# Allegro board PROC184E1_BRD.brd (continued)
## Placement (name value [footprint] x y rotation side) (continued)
C833  0.1uF  [CAP0201_0-5]  115.53 90.17 90 bottom
C834  0.1uF  [CAP0201_0-5]  128.68 90.2 45 bottom
C835  0.1uF  [CAP0201_0-5]  124.32 90.37 90 bottom
C836  0.1uF  [CAP0201_0-5]  119.92 89.43 135 bottom
C837  0.1uF  [CAP0201_0-5]  113.5 89.84 0 bottom
C838  0.01uF  [CAP0402_0-75]  158.68 89.78 270 bottom
C839  0.01uF  [CAP0402_0-75]  156.4 89.79 270 bottom
C840  0.1uF  [CAP0201_0-5]  135.59 102.29 90 bottom
C841  0.1uF  [CAP0201_0-5]  114.74 90.17 90 bottom
C844  0.1uF  [CAP0201_0-5]  125.13 90.17 90 bottom
C845  0.1uF  [CAP0201_0-5]  125.92 90.17 90 bottom
C846  0.01uF  [CAP0402_0-75]  145.09 88.01 270 bottom
C847  0.1uF  [CAP0201_0-5]  123.93 89.41 135 bottom
C848  0.1uF  [CAP0201_0-5]  128.76 88.16 0 bottom
C849  1uF  [CAP0402_0-75]  142.35 99.09 0 bottom
C850  0.1uF  [CAP0201_0-5]  117.12 90.17 90 bottom
C851  0.1uF  [CAP0201_0-5]  112.71 88.62 225 bottom
C853  0.1uF  [CAP0201_0-5]  121.55 89.08 180 bottom
C854  0.1uF  [CAP0201_0-5]  134.63 87.25 0 bottom
C855  0.1uF  [CAP0201_0-5]  128.15 90.6 45 bottom
C856  0.1uF  [CAP0201_0-5]  116.72 89.03 0 bottom
C857  0.1uF  [CAP0201_0-5]  115.45 88.77 270 bottom
C858  0.1uF  [CAP0402_0-75]  67.93 88.53 270 bottom
C859  0.1uF  [CAP0201_0-5]  114.28 89.03 0 bottom
C860  0.1uF  [CAP0201_0-5]  132.9 87.25 0 bottom
C862  0.1uF  [CAP0201_0-5]  127.08 89.41 45 bottom
C863  0.1uF  [CAP0201_0-5]  111.92 89.84 180 bottom
C864  0.1uF  [CAP0201_0-5]  129.5 89.41 45 bottom
C865  0.1uF  [CAP0201_0-5]  114.89 84.4 45 bottom
C866  0.1uF  [CAP0201_0-5]  114.08 83.27 315 bottom
C867  0.1uF  [CAP0201_0-5]  123.12 88.62 45 bottom
C870  0.1uF  [CAP0201_0-5]  119.16 87.55 0 bottom
C872  0.01uF  [CAP0402_0-75]  155.53 86.44 90 bottom
C873  0.1uF  [CAP0201_0-5]  113.6 84.25 180 bottom
C874  0.1uF  [CAP0201_0-5]  122.31 87.05 315 bottom
C875  0.1uF  [CAP0201_0-5]  113.17 87.81 270 bottom
C877  0.01uF  [CAP0402_0-75]  158.68 86.6 270 bottom
C878  0.1uF  [CAP0201_0-5]  125.51 80.65 45 bottom
C879  0.1uF  [CAP0402_0-75]  42.82 86.19 0 bottom
C880  0.1uF  [CAP0201_0-5]  129.45 87.43 0 bottom
C881  0.1uF  [CAP0201_0-5]  126.32 84.23 0 bottom
C882  0.1uF  [CAP0402_0-75]  67.93 85.54 270 bottom
C883  0.1uF  [CAP0402_0-75]  50.81 85.48 90 bottom
C884  0.01uF  [CAP0402_0-75]  145.22 85.2 270 bottom
C885  0.1uF  [CAP0201_0-5]  115.04 82.27 315 bottom
C886  0.1uF  [CAP0402_0-75]  42.83 84.97 0 bottom
C887  0.1uF  [CAP0201_0-5]  123.91 78.64 180 bottom
C888  0.1uF  [CAP0201_0-5]  119.13 79.43 180 bottom
C889  0.1uF  [CAP0201_0-5]  115.93 85.04 180 bottom
C890  0.01uF  [CAP0402_0-75]  155.74 84.02 270 bottom
C891  47uF  [CAP1210_2-75]  179 84.23 180 bottom
C892  47uF  [CAP1210_2-75]  173.16 84.23 0 bottom
C893  0.1uF  [CAP0201_0-5]  112.76 82.25 225 bottom
C894  0.1uF  [CAP0201_0-5]  124.32 87.81 90 bottom
C895  0.1uF  [CAP0201_0-5]  119.92 85.04 0 bottom
C896  0.1uF  [CAP0402_0-75]  67.93 83.48 270 bottom
C897  0.01uF  [CAP0402_0-75]  158.68 83.43 270 bottom
C898  0.1uF  [CAP0201_0-5]  117.1 81.56 90 bottom
C899  0.1uF  [CAP0201_0-5]  110.7 82.96 90 bottom
C900  0.1uF  [CAP0201_0-5]  111.97 76.2 180 bottom
C901  4.7uF  [CAP0402_0-75]  101.91 85.3 180 bottom
C902  0.1uF  [CAP0402_0-75]  25.92 82.84 0 bottom
C904  0.1uF  [CAP0201_0-5]  127.08 86.49 0 bottom
C905  10uF  [CAP0603_1-25]  109.94 63.88 180 bottom
C906  0.1uF  [CAP0402_0-75]  219.64 82.07 0 bottom
C907  0.1uF  [CAP0402_0-75]  241.41 81.98 270 bottom
C908  0.1uF  [CAP0201_0-5]  126.91 77.22 45 bottom
C909  0.1uF  [CAP0201_0-5]  116.72 83.03 225 bottom
C910  0.1uF  [CAP0201_0-5]  119.11 78.21 45 bottom
C911  0.1uF  [CAP0201_0-5]  110.32 70.23 45 bottom
C912  0.1uF  [CAP0402_0-75]  158.3 81.77 0 bottom
C913  0.01uF  [CAP0402_0-75]  144.33 89.66 90 bottom
C914  0.01uF  [CAP0402_0-75]  153.6 81.66 0 bottom
C915  0.01uF  [CAP0402_0-75]  148.4 81.66 180 bottom
C916  0.1uF  [CAP0201_0-5]  125.13 81.59 90 bottom
C917  9pF  [CAP0402_0-75]  186.62 81.69 90 bottom
C918  1uF  [CAP0402_0-75]  101.41 81.69 180 bottom
C919  0.1uF  [CAP0402_0-75]  229.93 81.29 90 bottom
C920  22uF  [CAP0805_1-25]  98.87 81.19 180 bottom
C921  0.1uF  [CAP0201_0-5]  114.13 82.35 315 bottom
C922  0.1uF  [CAP0201_0-5]  121.47 86.56 180 bottom
C923  10uF  [CAP0805_1-5]  15.5 81 270 bottom
C925  0.1uF  [CAP0201_0-5]  111.11 69.44 45 bottom
C926  0.1uF  [CAP0402_0-75]  17.27 80.88 270 bottom
C927  1uF  [CAP0402_0-75]  112.23 80.67 90 bottom
C928  10uF  [CAP0805_1-5]  177.86 80.68 180 bottom
C929  10uF  [CAP0805_1-5]  174.3 80.68 0 bottom
C930  1uF  [CAP0402_0-75]  101.41 80.68 180 bottom
C931  0.1uF  [CAP0402_0-75]  67.93 80.5 270 bottom
C932  0.1uF  [CAP0201_0-5]  121.57 85.83 180 bottom
C933  0.01uF  [CAP0402_0-75]  153.47 80.25 180 bottom
C934  0.01uF  [CAP0402_0-75]  151.06 80.25 180 bottom
C935  0.01uF  [CAP0402_0-75]  148.9 80.25 180 bottom
C936  0.01uF  [CAP0402_0-75]  146.61 80.25 180 bottom
C937  10uF  [CAP0603_1-25]  219.64 80.17 0 bottom
C938  0.1uF  [CAP0201_0-5]  111.16 80.21 180 bottom
C939  1uF  [CAP0402_0-75]  104.22 79.61 180 bottom
C940  0.1uF  [CAP0201_0-5]  111.9 68.61 45 bottom
C941  9pF  [CAP0402_0-75]  186.62 79.53 270 bottom
C942  10uF  [CAP0805_1-5#2]  156.27 79.53 0 bottom
C943  0.1uF  [CAP0201_0-5]  112.05 79.45 180 bottom
C944  0.1uF  [CAP0201_0-5]  128.71 81.03 0 bottom
C947  0.1uF  [CAP0201_0-5]  127.9 78.23 225 bottom
C948  1uF  [CAP0402_0-75]  153.48 79.28 0 bottom
C949  0.1uF  [CAP0402_0-75]  229.93 79.13 90 bottom
C950  0.1uF  [CAP0201_0-5]  113.52 70.23 225 bottom
C951  0.1uF  [CAP0402_0-75]  67.93 78.43 270 bottom
C952  0.01uF  [CAP0402_0-75]  153.48 78.34 0 bottom
C953  0.01uF  [CAP0402_0-75]  151.19 78.34 0 bottom
C954  0.01uF  [CAP0402_0-75]  149.03 78.34 0 bottom
C955  0.01uF  [CAP0402_0-75]  146.62 78.34 0 bottom
C957  0.1uF  [CAP0201_0-5]  111.16 78.99 135 bottom
C958  0.1uF  [CAP0201_0-5]  111.16 77.8 180 bottom
C959  0.1uF  [CAP0201_0-5]  127.97 82.63 0 bottom
C960  0.1uF  [CAP0201_0-5]  127.92 88.62 45 bottom
C962  0.1uF  [CAP0201_0-5]  133.54 68.22 0 bottom
C963  0.1uF  [CAP0402_0-75]  172.01 77.51 0 bottom
C965  0.1uF  [CAP0201_0-5]  110.37 77.04 180 bottom
C966  0.1uF  [CAP0201_0-5]  110.37 78.41 180 bottom
C967  0.1uF  [CAP0201_0-5]  125.74 86.82 135 bottom
C968  1uF  [CAP0402_0-75]  101.41 77.12 180 bottom
C969  0.1uF  [CAP0201_0-5]  127.14 75.03 315 bottom
C970  0.1uF  [CAP0201_0-5]  110.37 76.35 180 bottom
C971  0.1uF  [CAP0201_0-5]  115.76 75.54 0 bottom
C972  0.1uF  [CAP0201_0-5]  114.13 77.39 90 bottom
C973  2.2uF  [CAP0603_1]  176.21 76.74 270 bottom
C974  1uF  [CAP0402_0-75]  111.92 77.11 180 bottom
C976  10uF  [CAP0603_1-25]  112.68 63.88 180 bottom
C977  0.1uF  [CAP0402_0-75]  179.83 76.52 180 bottom
C978  0.01uF  [CAP0402_0-75]  157.75 76.43 0 bottom
C979  0.1uF  [CAP0402_0-75]  145.93 81.64 180 bottom
C980  0.1uF  [CAP0402_0-75]  21.83 76.41 270 bottom
C981  0.01uF  [CAP0402_0-75]  148.39 60.32 180 bottom
C982  0.01uF  [CAP0402_0-75]  153.6 60.32 0 bottom
C983  0.1uF  [CAP0201_0-5]  118.19 87.15 315 bottom
C984  0.1uF  [CAP0201_0-5]  115.93 76.15 180 bottom
C985  2.2uF  [CAP0603_1]  172.65 76.11 0 bottom
C986  0.1uF  [CAP0201_0-5]  113.44 65.53 270 bottom
C988  0.1uF  [CAP0402_0-75]  67.92 75.91 270 bottom
C989  0.1uF  [CAP0201_0-5]  111.11 74.68 180 bottom
C990  0.1uF  [CAP0201_0-5]  116.73 76.62 135 bottom
C992  0.1uF  [CAP0201_0-5]  113.76 76.4 135 bottom
C993  0.1uF  [CAP0201_0-5]  125.84 88.65 90 bottom
C994  47uF  [CAP1210_2-75]  185.61 75.6 90 bottom
C995  0.1uF  [CAP0201_0-5]  125.1 87.94 270 bottom
C996  0.1uF  [CAP0201_0-5]  120.33 86.21 90 bottom
C997  0.1uF  [CAP0201_0-5]  123.93 75.41 180 bottom
C999  0.1uF  [CAP0201_0-5]  117.18 77.45 90 bottom
C1000  0.01uF  [CAP0402_0-75]  160.97 75.22 270 bottom
C1001  10uF  [CAP0805_1-5]  182.79 75.09 90 bottom
C1002  0.1uF  [CAP0201_0-5]  111.11 75.44 180 bottom
C1003  0.1uF  [CAP0201_0-5]  118.32 75.41 180 bottom
C1004  0.1uF  [CAP0201_0-5]  114.28 65.53 270 bottom
C1005  0.1uF  [CAP0201_0-5]  113.75 75.59 135 bottom
C1006  0.1uF  [CAP0201_0-5]  112.3 75.03 90 bottom
C1007  0.1uF  [CAP0201_0-5]  125.54 75.01 135 bottom
C1008  0.1uF  [CAP0201_0-5]  111.08 81.05 180 bottom
C1009  0.1uF  [CAP0201_0-5]  113.44 67.08 270 bottom
C1010  0.01uF  [CAP0402_0-75]  158.41 74.63 90 bottom
C1011  0.1uF  [CAP0201_0-5]  134.17 90.35 315 bottom
C1012  0.1uF  [CAP0201_0-5]  110.47 73.91 180 bottom
C1014  0.1uF  [CAP0201_0-5]  112.76 72.24 180 bottom
C1015  2.2uF  [CAP0603_1]  173.36 74.07 0 bottom
C1016  0.1uF  [CAP0402_0-75]  67.92 73.85 270 bottom
C1017  0.1uF  [CAP0201_0-5]  114.28 67.08 270 bottom
C1018  4.7uF  [CAP0402_0-75]  101.41 73.82 180 bottom
C1019  0.1uF  [CAP0201_0-5]  112.71 73.08 180 bottom
C1020  0.1uF  [CAP0402_0-75]  21.07 73.62 0 bottom
C1021  0.1uF  [CAP0201_0-5]  115.48 73.43 270 bottom
C1022  0.1uF  [CAP0201_0-5]  114.71 72.62 270 bottom
C1023  0.1uF  [CAP0402_0-75]  25.56 73.01 180 bottom
C1024  0.01uF  [CAP0402_0-75]  145.22 63.88 270 bottom
C1025  2.2uF  [CAP0603_1]  173.36 72.8 0 bottom
C1026  1uF  [CAP0402_0-75]  101.41 72.68 180 bottom
C1027  0.1uF  [CAP0201_0-5]  109.58 75.44 180 bottom
C1028  0.1uF  [CAP0201_0-5]  113.95 73.33 270 bottom
C1029  0.1uF  [CAP0201_0-5]  124.65 74.5 180 bottom
C1031  22uF  [CAP0805_1-25]  96.07 72.04 180 bottom
C1032  0.1uF  [CAP0201_0-5]  116.72 73.03 0 bottom
C1033  0.01uF  [CAP0402_0-75]  155.53 65.1 90 bottom
C1034  0.1uF  [CAP0201_0-5]  111.92 73.74 180 bottom
C1035  2.2uF  [CAP0603_1]  173.36 71.53 0 bottom
C1036  1uF  [CAP0402_0-75]  101.41 71.53 180 bottom
C1037  0.01uF  [CAP0402_0-75]  158.41 71.45 90 bottom
C1038  10uF  [CAP1210_2-75]  215.45 71.28 0 bottom
C1039  2.2uF  [CAP0603_1]  171.48 71.08 270 bottom
C1040  0.1uF  [CAP0402_0-75]  67.93 70.4 270 bottom
C1041  1uF  [CAP0402_0-75]  101.41 76.05 180 bottom
C1042  4.7uF  [CAP0402_0-75]  98.99 70.39 180 bottom
C1043  0.1uF  [CAP0402_0-75]  43.47 70.24 0 bottom
C1044  0.01uF  [CAP0402_0-75]  145.09 66.67 270 bottom
C1045  0.1uF  [CAP0201_0-5]  98.99 69.5 180 bottom
C1046  1uF  [CAP0402_0-75]  115.53 71.91 270 bottom
C1047  1uF  [CAP0402_0-75]  114.71 74.22 270 bottom
C1048  1uF  [CAP0402_0-75]  113.9 71.86 270 bottom
C1049  10uF  [CAP0603_1-25]  43.7 68.84 0 bottom
C1050  0.1uF  [CAP0402_0-75]  200.55 68.74 90 bottom
C1051  0.01uF  [CAP0402_0-75]  144.31 68.29 90 bottom
C1052  0.1uF  [CAP0402_0-75]  67.93 68.34 270 bottom
C1053  0.01uF  [CAP0402_0-75]  158.41 68.28 90 bottom
C1054  0.01uF  [CAP0402_0-75]  156.37 68.5 270 bottom
C1055  10uF  [CAP1210_2-75]  215.45 67.72 0 bottom
C1056  0.1uF  [CAP0402_0-75]  56.96 67.62 270 bottom
C1057  0.1uF  [CAP0402_0-75]  239.55 67.47 0 bottom
C1058  0.1uF  [CAP0402_0-75]  237.49 67.47 0 bottom
C1059  10uF  [CAP0805_1-5]  177.86 67.47 180 bottom
C1060  10uF  [CAP0805_1-5]  174.3 67.47 0 bottom
C1062  0.1uF  [CAP0201_0-5]  126.6 74.22 270 bottom
C1063  0.1uF  [CAP0402_0-75]  42.5 66.13 0 bottom
C1064  0.1uF  [CAP0402_0-75]  56.96 65.64 90 bottom
C1065  0.1uF  [CAP0402_0-75]  67.93 65.58 270 bottom
C1066  0.01uF  [CAP0402_0-75]  156.39 71.24 270 bottom
C1067  1uF  [CAP0402_0-75]  96.93 65.18 180 bottom
C1068  0.01uF  [CAP0402_0-75]  145.22 71.62 270 bottom
C1069  10uF  [CAP0603_1]  158.41 64.47 90 bottom
C1070  1uF  [CAP0402_0-75]  116.38 63.5 270 bottom
C1071  47uF  [CAP1210_2-75]  179 63.99 180 bottom
C1072  47uF  [CAP1210_2-75]  173.16 63.91 0 bottom
C1073  0.1uF  [CAP0402_0-75]  67.93 63.52 270 bottom
C1074  0.01uF  [CAP0402_0-75]  145.83 73.61 90 bottom
C1075  0.1uF  [CAP0402_0-75]  194.24 61.83 270 bottom
C1077  1uF  [CAP0402_0-75]  139.45 57.33 270 bottom
C1078  1uF  [CAP0402_0-75]  110.63 59.26 270 bottom
C1079  0.1uF  [CAP0402_0-75]  130.39 49 180 top
C1080  1uF  [CAP0402_0-75]  119.54 48.89 180 top
C1081  0.1uF  [CAP0402_0-75]  144.97 75.61 270 bottom
C1082  0.1uF  [CAP0402_0-75]  43.37 61.12 0 bottom
C1083  0.01uF  [CAP0402_0-75]  149.53 76.45 0 bottom
C1084  0.01uF  [CAP0402_0-75]  152.33 76.45 180 bottom
C1085  0.01uF  [CAP0402_0-75]  154.87 76.45 180 bottom
C1086  0.1uF  [CAP0402_0-75]  130.39 47.81 180 top
C1089  10uF  [CAP0603_1-25]  43.49 59.72 0 bottom
C1090  0.01uF  [CAP0402_0-75]  148.24 59.34 180 bottom
C1091  0.01uF  [CAP0402_0-75]  155.61 58.75 0 bottom
C1092  0.01uF  [CAP0402_0-75]  153.45 58.75 0 bottom
C1093  10uF  [CAP0805_1-5#2]  137.98 56.93 270 bottom
C1095  0.1uF  [CAP0402_0-75]  137.6 45.23 0 bottom
C1096  0.1uF  [CAP0402_0-75]  135.54 45.23 180 bottom
C1097  0.1uF  [CAP0402_0-75]  56.98 56.2 0 bottom
C1098  4.7uF  [CAP0402_0-75]  135.54 44.09 180 bottom
C1105  0.1uF  [CAP0402_0-75]  193.41 54.01 90 bottom
C1117  0.1uF  [CAP0402_0-75]  54.34 50.12 180 bottom
C1118  0.1uF  [CAP0402_0-75]  64.19 49.61 0 bottom
C1120  0.1uF  [CAP0201_0-5]  71.94 49.44 90 bottom
C1122  0.01uF  [CAP0402_0-75]  194.09 49.19 0 bottom
C1123  0.1uF  [CAP0402_0-75]  13.35 48.72 90 bottom
C1124  0.1uF  [CAP0402_0-75]  26.06 47.64 90 bottom
C1131  0.1uF  [CAP0402_0-75]  54.2 45.37 0 bottom
C1134  0.1uF  [CAP0402_0-75]  63.86 44.76 270 bottom
C1135  0.1uF  [CAP0201_0-5]  72.07 44.56 90 bottom
C1137  0.1uF  [CAP0402_0-75]  19.4 44.25 90 bottom
C1138  0.1uF  [CAP0402_0-75]  17.98 44.25 270 bottom
C1161  0.01uF  [CAP0402_0-75]  45.99 41.75 180 bottom
C1162  10uF  [CAP0603_1-25]  204.83 41.47 0 bottom
C1163  10uF  [CAP0603_1-25]  199.37 40.43 180 bottom
C1164  0.1uF  [CAP0402_0-75]  204.71 39.93 0 bottom
C1165  0.1uF  [CAP0402_0-75]  199.37 38.89 180 bottom
C1166  10uF  [CAP1210_2-75]  11.43 38.77 90 bottom
C1167  0.1uF  [CAP0603_1]  14.35 38.64 90 bottom
C1168  10uF  [CAP0603_1-25]  43.67 37.59 90 bottom
C1169  0.01uF  [CAP0402_0-75]  81.55 35.34 0 bottom
C1170  0.1uF  [CAP0402_0-75]  43.87 35.34 270 bottom
C1171  0.1uF  [CAP0402_0-75]  42.6 35.34 270 bottom
C1172  18pF  [CAP0402_0-75]  139 34.58 0 bottom
C1173  18pF  [CAP0402_0-75]  137.06 34.58 180 bottom
C1174  0.1uF  [CAP0402_0-75]  183.24 32.42 180 bottom
C1175  0.1uF  [CAP0402_0-75]  166.94 31.45 0 bottom
C1176  1uF  [CAP0402_0-75]  83.65 31.4 180 bottom
C1177  0.1uF  [CAP0402_0-75]  57.94 30.46 270 bottom
C1178  1uF  [CAP0402_0-75]  95.33 30.34 90 bottom
C1179  10uF  [CAP0805_1-5]  93.56 30.34 90 bottom
C1180  1uF  [CAP0402_0-75]  69.68 30.34 90 bottom
C1181  10uF  [CAP0805_1-5]  67.9 30.34 90 bottom
C1182  0.1uF  [CAP0402_0-75]  83.65 30.13 0 bottom
C1183  1uF  [CAP0402_0-75]  167.7 29.63 90 bottom
C1184  0.1uF  [CAP0402_0-75]  166.43 29.63 90 bottom
C1185  0.1uF  [CAP0402_0-75]  160.72 29.03 90 bottom
C1186  10uF  [CAP0805_1-5]  90.08 28.76 90 bottom
C1187  10uF  [CAP0805_1-5]  64.42 28.76 90 bottom
C1188  1uF  [CAP0402_0-75]  91.78 28.71 90 bottom
C1189  1uF  [CAP0402_0-75]  66.12 28.71 90 bottom
C1190  0.1uF  [CAP0402_0-75]  93.91 27.77 180 bottom
C1191  0.1uF  [CAP0402_0-75]  68.26 27.77 180 bottom
C1192  2.2uF  [CAP0402_0-75]  180.63 27.34 90 bottom
C1193  3300pF  [CAP0402_0-75]  26.65 27.33 0 bottom
C1194  10uF  [CAP0805_1-5]  35.91 26.61 270 bottom
C1195  10uF  [CAP0805_1-5]  33.73 26.61 270 bottom
C1196  0.01uF  [CAP0402_0-75]  87.92 25.73 90 bottom
C1197  0.1uF  [CAP0402_0-75]  93.91 25.71 180 bottom
C1198  0.1uF  [CAP0402_0-75]  68.26 25.71 180 bottom
C1199  0.1uF  [CAP0402_0-75]  136.56 25.53 180 bottom
C1200  1uF  [CAP0402_0-75]  58.35 25.48 180 bottom
C1201  680pF  [CAP0402_0-75]  29.07 25.23 0 bottom
C1202  680pF  [CAP0402_0-75]  24.55 25.16 0 bottom
C1203  4.7uF  [CAP0603_1]  60.5 25.1 270 bottom
C1204  0.1uF  [CAP0402_0-75]  83.65 24.92 0 bottom
C1205  0.1uF  [CAP0402_0-75]  230.38 24.72 90 bottom
C1206  0.1uF  [CAP0402_0-75]  58.35 24.21 0 bottom
C1207  27pF  [CAP0402_0-75]  93.32 24.04 270 bottom
C1208  27pF  [CAP0402_0-75]  67.66 24.04 270 bottom
C1209  1uF  [CAP0402_0-75]  117.96 23.57 180 bottom
C1210  10uF  [CAP0805_1-5]  83.65 23.27 180 bottom
C1211  10uF  [CAP0805_1-5]  31.1 23.1 90 bottom
C1212  10uF  [CAP0603_1-25]  176.11 22.99 90 bottom
C1213  1uF  [CAP0402_0-75]  177.69 22.99 90 bottom
C1214  0.1uF  [CAP0402_0-75]  224.18 22.63 90 bottom
C1215  220uF_10V  [CAPT3528T_1-25]  19.48 22.56 180 bottom
C1216  0.1uF  [CAP0402_0-75]  214.62 22.25 270 bottom
C1217  0.1uF  [CAP0402_0-75]  182.67 22.18 270 bottom
C1218  27pF  [CAP0402_0-75]  93.32 22 90 bottom
C1219  27pF  [CAP0402_0-75]  67.66 22 90 bottom
C1220  0.01uF  [CAP0402_0-75]  62.62 19.81 90 bottom
C1221  0.1uF  [CAP0402_0-75]  101.11 19.57 270 bottom
C1222  0.1uF  [CAP0402_0-75]  99.61 19.57 270 bottom
C1223  0.1uF  [CAP0402_0-75]  98.11 19.57 270 bottom
C1224  0.1uF  [CAP0402_0-75]  75.46 19.57 270 bottom
C1225  0.1uF  [CAP0402_0-75]  73.96 19.57 270 bottom
C1226  0.1uF  [CAP0402_0-75]  72.46 19.57 270 bottom
C1227  10uF  [CAP0805_1-5]  44.11 19.31 180 bottom
C1228  0.1uF  [CAP0402_0-75]  58.35 19.01 0 bottom
C1229  220uF_10V  [CAPT3528T_1-25]  19.48 18.88 180 bottom
C1230  0.1uF  [CAP0402_0-75]  32.12 17.39 0 bottom
C1231  10uF  [CAP0805_1-5]  58.35 17.36 180 bottom
C1232  0.1uF  [CAP0402_0-75]  188.42 17.14 270 bottom
C1233  680pF  [CAP0402_0-75]  30.07 16.26 0 bottom
C1234  680pF  [CAP0402_0-75]  25.62 16.26 0 bottom
C1235  0.1uF  [CAP0402_0-75]  197.71 16.21 270 bottom
C1236  0.1uF  [CAP0402_0-75]  214.55 16.17 270 bottom
C1237  0.1uF  [CAP0402_0-75]  23.44 16.02 180 bottom
C1238  10uF  [CAP0805_1-5]  42.1 15.45 0 bottom
C1239  0.1uF  [CAP0402_0-75]  223.8 15.4 270 bottom
C1240  10uF  [CAP0805_1-5]  56.57 15.1 0 bottom
C1241  0.1uF  [CAP0402_0-75]  231.84 14.72 180 bottom
C1242  3300pF  [CAP0402_0-75]  27.84 14.17 0 bottom
C1243  4.7uF  [CAP0603_1]  187.9 13.27 270 bottom
C1244  4.7uF  [CAP0603_1]  214 13.27 270 bottom
C1245  4.7uF  [CAP0603_1]  190.54 13.23 90 bottom
C1246  4.7uF  [CAP0603_1]  216.64 13.23 90 bottom
C1247  1000pF  [CAP1206_1-75]  88.97 12.27 270 bottom
C1248  1000pF  [CAP1206_1-75]  63.9 12.24 270 bottom
C1249  10uF  [CAP0603_1-25]  21.27 12.1 180 bottom
C1250  0.1uF  [CAP0402_0-75]  21.27 10.57 180 bottom
C1251  0.01uF  [CAP0402_0-75]  197.29 10.45 0 bottom
C1252  0.1uF  [CAP0402_0-75]  199.96 10.25 0 bottom
C1253  0.01uF  [CAP0402_0-75]  219.9 9.96 0 bottom
C1254  0.1uF  [CAP0402_0-75]  222.56 9.76 0 bottom
C1255  2.2uF  [CAP0402_0-75]  199.96 9.1 0 bottom
C1256  2.2uF  [CAP0402_0-75]  222.56 8.62 0 bottom
C1257  10uF  [CAP0805_1-5]  192.08 7.65 90 bottom
C1258  0.1uF  [CAP0402_0-75]  193.79 7.65 90 bottom
C1259  0.1uF  [CAP0402_0-75]  21.27 7.27 180 bottom
C1260  10uF  [CAP0805_1-5]  214.69 7.17 90 bottom
C1261  0.1uF  [CAP0402_0-75]  216.39 7.17 90 bottom
C1262  10uF  [CAP0805_1-5]  28.94 7.14 270 bottom
C1263  10uF  [CAP0805_1-5]  26.75 7.14 270 bottom
C1264  0.1uF  [CAP0402_0-75]  202.84 6.35 180 bottom
C1265  10uF  [CAP0603_1-25]  21.27 5.75 180 bottom
C1266  0.1uF  [CAP0402_0-75]  121.53 173.82 270 bottom
C1267  0.1uF  [CAP0402_0-75]  96.01 172.83 180 bottom
C1268  0.1uF  [CAP0402_0-75]  130.71 26.54 90 bottom
C1269  0.1uF  [CAP0402_0-75]  73.47 66.67 180 top
C1271  0.1uF  [CAP0402_0-75]  67.88 92.2 270 top
C1290  100uF  [CAP1210_3]  96.86 91.59 270 top
C1291  100uF  [CAP1210_3]  90.36 92.53 270 top
C1292  100uF  [CAP1210_3]  112.45 106.96 270 top
C1293  100uF  [CAP1210_3]  113.67 115.77 180 top
C2582  100uF  [CAP1210_3]  137.88 106.97 270 bottom
C2583  100uF  [CAP1210_3]  148.27 106.97 270 bottom
C2584  100uF  [CAP1210_3]  144.71 106.97 270 bottom
C2585  100uF  [CAP1210_3]  141.16 106.97 270 bottom
C2586  100uF  [CAP1210_3]  95.56 108.49 0 bottom
C2587  100uF  [CAP1210_3]  95.56 101.89 0 bottom
C2588  100uF  [CAP1210_3]  96.86 90.74 270 bottom
C2589  100uF  [CAP1210_3]  95.56 105.19 0 bottom
C2590  100uF  [CAP1210_3]  90.23 92.53 270 bottom
C2591  100uF  [CAP1210_3]  93.5 92.53 270 bottom
C2592  100uF  [CAP1210_3]  95.56 98.58 0 bottom
D1  TPD1E05U06DPY  [DIO_DFN0402_0-5]  142.82 186.11 90 top
D2  TPD1E05U06DPY  [DIO_DFN0402_0-5]  155.82 186.11 90 top
D3  TPD1E05U06DPY  [DIO_DFN0402_0-5]  142.82 184.65 270 top
D4  TPD1E05U06DPY  [DIO_DFN0402_0-5]  155.82 184.65 270 top
D5  TPD1E05U06DPY  [DIO_DFN0402_0-5]  146.34 180.52 180 top
D6  TPD1E05U06DPY  [DIO_DFN0402_0-5]  147.8 180.52 0 top
D7  TPD1E05U06DPY  [DIO_DFN0402_0-5]  150.84 180.52 180 top
D8  TPD1E05U06DPY  [DIO_DFN0402_0-5]  152.3 180.52 0 top
D9  TPD1E05U06DPY  [DIO_DFN0402_0-5]  89.31 173.71 180 top
D10  TPD1E05U06DPY  [DIO_DFN0402_0-5]  90.98 173.71 0 top
D11  TPD1E05U06DPY  [DIO_DFN0402_0-5]  95.25 173.71 180 top
D12  TPD1E05U06DPY  [DIO_DFN0402_0-5]  96.93 173.71 0 top
D13  TPD1E05U06DPY  [DIO_DFN0402_0-5]  115.18 173.71 180 top
D14  TPD1E05U06DPY  [DIO_DFN0402_0-5]  116.85 173.71 0 top
D15  TPD1E05U06DPY  [DIO_DFN0402_0-5]  121.13 173.71 180 top
D16  TPD1E05U06DPY  [DIO_DFN0402_0-5]  122.8 173.71 0 top
D17  TPD1E05U06DPY  [DIO_DFN0402_0-5]  86.38 172.31 180 top
D18  TPD1E05U06DPY  [DIO_DFN0402_0-5]  88.06 172.31 0 top
D19  TPD1E05U06DPY  [DIO_DFN0402_0-5]  112.26 172.31 180 top
D20  TPD1E05U06DPY  [DIO_DFN0402_0-5]  113.93 172.31 0 top
D21  TPD1E05U06DPY  [DIO_DFN0402_0-5]  92.25 172.06 180 top
D22  TPD1E05U06DPY  [DIO_DFN0402_0-5]  93.93 172.06 0 top
D23  TPD1E05U06DPY  [DIO_DFN0402_0-5]  98.3 172.06 180 top
D24  TPD1E05U06DPY  [DIO_DFN0402_0-5]  99.98 172.06 0 top
D25  TPD1E05U06DPY  [DIO_DFN0402_0-5]  118.12 172.06 180 top
D26  TPD1E05U06DPY  [DIO_DFN0402_0-5]  119.8 172.06 0 top
D27  TPD1E05U06DPY  [DIO_DFN0402_0-5]  124.17 172.06 180 top
D28  TPD1E05U06DPY  [DIO_DFN0402_0-5]  125.85 172.06 0 top
D29  SMCJ58CA  [DIO_SMC_2-7]  227.52 171.97 0 top
D30  SZMM3Z10VST1G  [DIO_SOD323_1-1]  164.01 162.7 0 top
D31  RBR1MM60A  [DIO_SOD123F_0-9]  196.36 152.76 270 top
D32  RBR1MM60A  [DIO_SOD123F_0-9]  196.36 147.94 90 top
D33  TPD1E10B06DPYR  [DIO_DFN0402_0-5]  16.57 123.18 90 top
D34  RBR1MM60A  [DIO_SOD123F_0-9]  223.55 107.2 270 top
D35  RBR1MM60A  [DIO_SOD123F_0-9]  223.55 102.37 90 top
D36  SZMM3Z10VST1G  [DIO_SOD323_1-1]  89.73 64.28 180 top
D37  TPD1E10B06DPYR  [DIO_DFN0402_0-5]  19.71 59.21 90 top
D38  RBR1MM60A  [DIO_SOD123F_0-9]  212.5 58.15 270 top
D39  DDZ9678-7  [DIO_SOD123_1-5]  113.09 13.21 270 top
D40  MBRS410LT3G  [DIO_SMC]  170.29 183.8 270 bottom
D41  BZT52C13S  [DIO_SOD323]  206.82 147.53 180 bottom
D42  1N4148W-7-F  [DIO_SOD123_1-4]  18.04 37.62 180 bottom
D43  1N4148W-7-F  [DIO_SOD123_1-4]  18.04 35.08 180 bottom
D44  1N4148W-7-F  [DIO_SOD123_1-4]  14.1 33.56 270 bottom
D45  1N4148W-7-F  [DIO_SOD123_1-4]  11.31 33.56 270 bottom
F1  6.3A  [FUSEH_154004_380X200_SMD_3-9]  219.26 169.3 270 top
F2  6.3A  [FUSEH_154004_380X200_SMD_3-9]  203.01 165.89 90 top
FL1  0.47uF  [EMIFIL_NFM21P_0805]  114.52 162.82 180 top
FL2  0.47uF  [EMIFIL_NFM21P_0805]  88.07 161.7 270 top
FL3  0.47uF  [EMIFIL_NFM21P_0805]  101.79 160.14 270 top
FL4  0.47uF  [EMIFIL_NFM21P_0805]  101.79 156.71 90 top
FL5  0.47uF  [EMIFIL_NFM21P_0805]  84.51 151.71 0 top
FL6  0.47uF  [EMIFIL_NFM21P_0805]  113.25 150.63 180 top
FL7  120E  [EMIFIL_BLM18P_0603_0-8]  107.15 136.66 270 top
FL8  0.47uF  [EMIFIL_NFM21P_0805]  53.91 121.98 270 top
FL9  0.47uF  [EMIFIL_NFM21P_0805]  66.1 120.71 270 top
FL10  10uF  [EMIFIL_NFM18C_0603_0-7_TI]  165.46 119.22 270 top
FL11  10uF  [EMIFIL_NFM18C_0603_0-7_TI]  166.86 119.22 270 top
FL12  10uF  [EMIFIL_NFM18C_0603_0-7_TI]  172.45 119.22 270 top
FL13  10uF  [EMIFIL_NFM18C_0603_0-7_TI]  173.85 119.22 270 top
FL14  10uF  [EMIFIL_NFM18C_0603_0-7_TI]  176.89 119.22 270 top
FL15  10uF  [EMIFIL_NFM18C_0603_0-7_TI]  178.29 119.22 270 top
FL16  10uF  [EMIFIL_NFM18C_0603_0-7_TI]  183.88 119.22 270 top
FL17  10uF  [EMIFIL_NFM18C_0603_0-7_TI]  185.28 119.22 270 top
FL18  10uF  [EMIFIL_NFM18C_0603_0-7_TI]  188.07 119.22 270 top
FL19  10uF  [EMIFIL_NFM18C_0603_0-7_TI]  189.47 119.22 270 top
FL20  10uF  [EMIFIL_NFM18C_0603_0-7_TI]  195.06 119.22 270 top
FL21  10uF  [EMIFIL_NFM18C_0603_0-7_TI]  196.45 119.22 270 top
FL22  10uF  [EMIFIL_NFM18C_0603_0-7_TI]  75.88 117.89 0 top
FL23  10uF  [EMIFIL_NFM18C_0603_0-7_TI]  75.88 116.49 0 top
FL24  10uF  [EMIFIL_NFM18C_0603_0-7_TI]  75.88 110.9 0 top
FL25  10uF  [EMIFIL_NFM18C_0603_0-7_TI]  75.88 109.51 0 top
FL26  0.47uF  [EMIFIL_NFM21P_0805]  56.38 109.13 0 top
FL27  0.47uF  [EMIFIL_NFM21P_0805]  59.91 109.13 180 top
FL32  10uF  [EMIFIL_NFM18C_0603_0-7_TI]  75.88 106.71 0 top
FL33  10uF  [EMIFIL_NFM18C_0603_0-7_TI]  75.88 105.32 0 top
FL34  10uF  [EMIFIL_NFM18C_0603_0-7_TI]  75.88 99.73 0 top
FL35  10uF  [EMIFIL_NFM18C_0603_0-7_TI]  75.88 98.33 0 top
FL40  1uF  [EMIFIL_NFM15CC_0402_0-5_TI]  173.4 87.41 180 top
FL41  1uF  [EMIFIL_NFM15CC_0402_0-5_TI]  178.76 87.41 180 top
FL42  120E  [EMIFIL_BLM15A_0402_0-6]  96.45 70.9 0 top
FL43  10uF  [EMIFIL_NFM18C_0603_0-7_TI]  88.83 68.23 0 top
FL44  10uF  [EMIFIL_NFM18C_0603_0-7_TI]  91.75 68.23 0 top
FL45  1uF  [EMIFIL_NFM15CC_0402_0-5_TI]  94.17 68.23 0 top
FL46  1uF  [EMIFIL_NFM15CC_0402_0-5_TI]  96.33 68.23 0 top
FL47  1uF  [EMIFIL_NFM15CC_0402_0-5_TI]  173.4 65.9 0 top
FL48  1uF  [EMIFIL_NFM15CC_0402_0-5_TI]  178.76 65.9 0 top
FL56  120E  [EMIFIL_BLM15A_0402_0-6]  40.83 29.83 180 top
FL57  120E  [EMIFIL_BLM15A_0402_0-6]  56.37 19.41 270 top
FL58  120E  [EMIFIL_BLM15A_0402_0-6]  59.11 9.18 270 top
FL59  120E  [EMIFIL_BLM15A_0402_0-6]  24.57 7.75 90 top
FL60  120E  [EMIFIL_BLM18A_0603]  142.02 155.35 90 bottom
FL61  120E  [EMIFIL_BLM18A_0603]  153.09 151.54 90 bottom
FL62  120E  [EMIFIL_BLM18A_0603]  137.68 150.43 90 bottom
FL63  120E  [EMIFIL_BLM18P_0603_0-8]  99.24 134.92 180 bottom
FL65  120E  [EMIFIL_BLM15A_0402_0-6]  129.6 113.29 270 bottom
FL66  120E  [EMIFIL_BLM15A_0402_0-6]  126.04 113.29 270 bottom
FL67  120E  [EMIFIL_BLM15A_0402_0-6]  122.49 113.29 90 bottom
FL70  120E  [EMIFIL_BLM15A_0402_0-6]  114.13 113.29 270 bottom
FL71  120E  [EMIFIL_BLM15A_0402_0-6]  111.72 113.29 270 bottom
FL76  120E  [EMIFIL_BLM15A_0402_0-6]  106.76 111.29 90 bottom
FL81  120E  [EMIFIL_BLM15A_0402_0-6]  106.51 108.85 270 bottom
FL82  120E  [EMIFIL_BLM15A_0402_0-6]  132.01 107.97 270 bottom
FL83  120E  [EMIFIL_BLM15A_0402_0-6]  135.57 107.97 270 bottom
FL84  120E  [EMIFIL_BLM15A_0402_0-6]  128.46 107.97 270 bottom
FL86  120E  [EMIFIL_BLM15A_0402_0-6]  121.34 107.97 90 bottom
FL87  120E  [EMIFIL_BLM15A_0402_0-6]  117.79 107.97 270 bottom
FL89  120E  [EMIFIL_BLM15A_0402_0-6]  110.57 107.97 270 bottom
FL94  120E  [EMIFIL_BLM15A_0402_0-6]  149.04 103.43 270 bottom
FL95  0E  [RES0402_0-5#2]  159.41 103.45 90 bottom
FL96  120E  [EMIFIL_BLM15A_0402_0-6]  155.95 103.45 90 bottom
FL97  120E  [EMIFIL_BLM15A_0402_0-6]  152.5 103.45 90 bottom
FL98  120E  [EMIFIL_BLM18A_0603]  176.49 101.18 270 bottom
FL122  1uF  [EMIFIL_NFM15CC_0402_0-5_TI]  120.35 82.07 90 bottom
FL132  120E  [EMIFIL_BLM15A_0402_0-6]  110.63 62.26 90 bottom
FL137  1uF  [EMIFIL_NFM15CC_0402_0-5_TI]  121.93 84.46 90 bottom
FL141  1uF  [EMIFIL_NFM15CC_0402_0-5_TI]  123.53 84.46 90 bottom
FL150  1uF  [EMIFIL_NFM15CC_0402_0-5_TI]  101.41 79.53 180 bottom
FL151  120E  [EMIFIL_BLM31KN_1206_1-8]  90.84 78.92 0 bottom
FL154  1uF  [EMIFIL_NFM15CC_0402_0-5_TI]  118.7 81.53 270 bottom
FL161  0E  [RES0402_0-5#2]  155.89 77.76 0 bottom
FL170  1uF  [EMIFIL_NFM15CC_0402_0-5_TI]  115.04 76.71 225 bottom
FL175  120E  [EMIFIL_BLM15A_0402_0-6]  114.33 63.37 90 bottom
FL176  120E  [EMIFIL_BLM15A_0402_0-6]  101.41 74.96 180 bottom
FL177  1uF  [EMIFIL_NFM15CC_0402_0-5_TI]  116.72 75.03 225 bottom
FL193  1uF  [EMIFIL_NFM15CC_0402_0-5_TI]  98.99 72.04 180 bottom
FL194  120E  [EMIFIL_BLM31KN_1206_1-8]  92.11 71.63 0 bottom
FL196  0E  [RES0402_0-5#2]  136.46 57.31 270 bottom
FL198  120E  [EMIFIL_BLM15A_0402_0-6]  21.9 8.92 90 bottom
J1  CON_MUSB-B_5_F  [CON_MUSBB5_1051640001_S_R_S_2-5]  20.11 188.53 180 top
J2  HDR_1X4  [HDR_1X4_61300411121_S_T_8-6]  132.48 187.63 180 top
J3  CON_TRBLK_1X2  [CON_TB1X2_1803277_P_R_T_7-3]  203.63 183.86 180 top
J4  CON_USB-C_24_F  [CON_USBC24_2012670_S_R_S_3-9]  149.32 186.62 180 top
J5  CON_USB-A_8_F  [CON_USBA8_AU-Y1008-2_S_R_T_15-5]  47.92 179.09 180 top
J6  HDR_1X3  [HDR_3X1_100_S_T]  196.94 183.19 270 top
J7  CON_POWERJACK4_PD-40S  [CON_POWERJACK4_PD-40S_S_R_T_15]  227.1 179.11 0 top
J8  CON_MUSB_20_F  [CON_USB20_472720001_S_R_T_7]  95.09 184.28 180 top
J9  CON_MUSB_20_F  [CON_USB20_472720001_S_R_T_7]  120.96 184.28 180 top
J10  CON_PMC_2X20_F  [CON_PMC2X20_QSH-020-01-D-DP-A_S_S_S_3-4]  69.33 183.46 180 top
J14  CON_PCIE_2X32  [CON_PCIE2X32_10142333-10111_S_S_T_11]  20.02 156.97 0 top
J17  CON_PCIE_2X32  [CON_PCIE2X32_10142333-10111_S_S_T_11]  20.02 136.65 0 top
J23  CON_PMC_2X30_F  [CON_PMC2X30_QSH-030-01-D-A_S_S_S_3-3]  13.25 90.68 90 top
J24  HDR_1X3  [HDR_1X3_440054-3_S_T_6-4]  239.5 78.88 270 top
J25  HDR_1X3  [HDR_3X1_100_S_T]  13.01 72.17 90 top
J26  HDR_6X1  [HDR_6X1_100_S_T]  8.02 72.17 90 top
J27  HDR_2X10  [HDR_2X10_TSW_100_S_T]  7.67 52.32 180 top
J28  HDR_1X4  [HDR_1X4_61300411121_S_T_8-6]  8.3 32.42 270 top
J29  CON_AUDIOJACK6_STX-4235  [CON_AV6_STX-4235-3-3_S_R_T_26]  8.5 15.72 270 top
J30  HDR_1X5  [HDR_1X5_68002-205_S_T_8-6]  241 22.89 90 top
J32  HDR_1X2  [HDR_1X2_68002-202_S_T_8-6]  125.28 13.88 270 top
J33  HDR_1X2  [HDR_1X2_68002-202_S_T_8-6]  135.09 13.88 270 top
J34  HDR_1X2  [HDR_1X2_68002-202_S_T_8-6]  144.89 13.88 270 top
J35  HDR_1X2  [HDR_1X2_68002-202_S_T_8-6]  154.69 13.88 270 top
J36  HDR_1X2  [HDR_1X2_68002-202_S_T_8-6]  164.5 13.88 270 top
J37  HDR_1X3  [HDR_1X3_78-74_S_T]  230.43 12.2 180 top
J39  CON_RJ45-14_LPJG16314A4NL  [CON_RJ45-14_LPJG16314A4NL_S_R_T_13-6]  69.11 16.77 0 top
J40  CON_RJ45-14_LPJG16314A4NL  [CON_RJ45-14_LPJG16314A4NL_S_R_T_13-6]  94.76 16.77 0 top
J41  HDR_1X4  [HDR_1X4_61300411121_S_T_8-6]  123.5 3.05 0 top
J42  HDR_1X3  [HDR_3X1_100_S_T]  133.16 3.05 0 top
J43  HDR_1X3  [HDR_3X1_100_S_T]  142.96 3.05 0 top
J44  HDR_1X3  [HDR_3X1_100_S_T]  152.76 3.05 0 top
J45  HDR_1X3  [HDR_3X1_100_S_T]  162.57 3.05 0 top
J46  HDR_1X3  [HDR_3X1_100_S_T]  172.37 3.05 0 top
J47  CON_TRBLK_1X2  [CON_TB1X2_1757242_P_R_T_8-6]  229.79 6.64 0 top
J48  CON_MUSB-B_5_F  [CON_MUSBB5_1051640001_S_R_S_2-5]  188.13 1.97 0 top
J49  CON_MUSB-B_5_F  [CON_MUSBB5_1051640001_S_R_S_2-5]  208.74 1.97 0 top
J50  CON_FLEX_40X1_FH12A-40S-0.5SH  [CON_FLEX40X1_FH12A_S_R_S]  10.71 143.85 90 bottom
J53  CON_SDCARD10_DM3BT-DSF-PEJS  [CON_SD10_DM3BT-DSF-PEJS_S_R_S_2-4]  14.52 115.22 90 bottom
J54  CON_PMC_2X60_F  [CON_PMC60X2_HQCD-060_S_S_S_3-3]  37.11 102.76 90 bottom
J55  CON_PMC_2X20_F  [CON_PMC2X20_QSH-020-01-D-DP-A_S_S_S_3-4]  210.42 87.34 180 bottom
J56  CON_PMC_2X60_F  [CON_PMC60X2_HQCD-060_S_S_S_3-3]  37.11 53.38 90 bottom
J57  CON_PMC_2X20_F  [CON_PMC2X20_QSH-020-01-D-DP-A_S_S_S_3-4]  207.44 33.66 180 bottom
L1  150E  [IND0805_M]  26.36 185.72 270 top
L2  90E  [IND4_DLW21H_90X60_SMD_1-4]  140.73 183.04 90 top
L3  90E  [IND4_DLW21H_90X60_SMD_1-4]  157.96 183.04 90 top
L4  10uH  [IND_ASPI-0603LR_270X270_SMD_3]  164.02 181.56 90 top
L5  90E  [IND4_DLW21H_90X60_SMD_1-4]  146.69 177.35 90 top
L6  90E  [IND4_DLW21H_90X60_SMD_1-4]  151.95 177.35 90 top
L7  90E  [IND4_DLW21H_90X60_SMD_1-4]  149.36 174.82 90 top
L8  90E  [IND4_DLW21H_90X60_SMD_1-4]  39.67 172.5 0 top
L9  90E  [IND4_DLW21H_90X60_SMD_1-4]  90.14 171.3 90 top
L10  90E  [IND4_DLW21H_90X60_SMD_1-4]  96.09 171.3 90 top
L11  90E  [IND4_DLW21H_90X60_SMD_1-4]  116.02 171.3 90 top
L12  90E  [IND4_DLW21H_90X60_SMD_1-4]  121.97 171.3 90 top
L13  90E  [IND4_DLW21H_90X60_SMD_1-4]  87.22 169.9 90 top
L14  90E  [IND4_DLW21H_90X60_SMD_1-4]  113.1 169.9 90 top
L15  90E  [IND4_DLW21H_90X60_SMD_1-4]  93.09 169.65 90 top
L16  90E  [IND4_DLW21H_90X60_SMD_1-4]  118.96 169.65 90 top
L17  90E  [IND4_DLW21H_90X60_SMD_1-4]  99.14 168.02 90 top
L18  90E  [IND4_DLW21H_90X60_SMD_1-4]  125.01 168.02 90 top
L19  220E  [IND0603_1]  77.91 167.67 0 top
L20  220E  [IND0603_1]  58.35 164.02 0 top
L21  1uH  [IND_HLP5050CE-1R0-01_530X510_SMD_3-5]  193.15 163.56 90 top
L22  1uH  [IND_HLP5050CE-1R0-01_530X510_SMD_3-5]  193.15 137.14 90 top
L23  1uH  [IND_HLP5050CE-1R0-01_530X510_SMD_3-5]  226.6 119.37 270 top
L24  0.1uH  [IND_XEL4030_170X170_SMD_3-2]  169.66 115.51 270 top
L25  0.1uH  [IND_XEL4030_170X170_SMD_3-2]  181.09 115.53 270 top
L26  0.1uH  [IND_XEL4030_170X170_SMD_3-2]  192.26 115.47 270 top
L27  0.1uH  [IND_XEL4030_170X170_SMD_3-2]  79.63 113.7 0 top
L28  0.1uH  [IND_XEL4030_170X170_SMD_3-2]  79.63 102.52 0 top
L29  4.7uH  [IND_XAL6060_260X270_SMD_6-1]  221.32 95.59 270 top
L30  0.22uH  [IND1008_1-2]  170.49 80.68 180 top
L31  0.22uH  [IND1008_1-2]  181.67 80.68 0 top
L32  0.22uH  [IND1008_1-2]  183.57 71.53 0 top
L33  0.22uH  [IND1008_1-2]  170.49 67.47 180 top
L34  0.22uH  [IND1008_1-2]  181.67 67.47 0 top
L35  9uH  [IND_SRP1250_550X530_SMD_5-2]  221.74 57.78 0 top
L36  1uH  [IND_NLCV25T-EFR_110X80_SMD_1-9]  173.77 23.59 270 top
L37  1uH  [IND_NLCV25T-EFR_110X80_SMD_1-9]  142.17 21.73 270 top
L38  90E  [IND4_DLW21H_90X60_SMD_1-4]  56.85 184.46 180 bottom
L39  90E  [IND4_DLW21H_90X60_SMD_1-4]  135.92 179.2 180 bottom
L40  220E  [IND0603_1]  186.3 13.37 270 bottom
L41  220E  [IND0603_1]  212.4 13.37 270 bottom
L42  220E  [IND0603_1]  219 12.66 180 bottom
L43  220E  [IND0603_1]  192.9 12.66 180 bottom
LD1  LS Q976-NR-1  [LED_0603_0-8]  30.33 189.06 0 top
LD2  5988170107F  [LED_0805_0-7]  184.72 186.6 90 top
LD3  5988170107F  [LED_0805_0-7]  187.89 186.5 90 top
LD4  5988170107F  [LED_0805_0-7]  190.65 186.5 90 top
LD5  5988110107F  [LED_0805]  193.33 186.5 90 top
LD6  LP L296-J2L2-25  [LED_0603_0-7]  30.33 186.4 0 top
LD7  5988170107F  [LED_0805_0-7]  241.13 126.83 0 top
LD8  5988170107F  [LED_0805_0-7]  241.13 123.02 0 top
LD9  5988170107F  [LED_0805_0-7]  241.13 119.21 0 top
LD10  5988170107F  [LED_0805_0-7]  187.46 64.57 270 top
LD11  5988170107F  [LED_0805_0-7]  196.44 5.03 180 top
LD12  5988170107F  [LED_0805_0-7]  217.95 2.87 180 top
NOREF  -  []  5 190.5 0 top
NOREF#2  -  [unnamed#2]  2.5 3.81 0 top
NOREF#3  -  [unnamed#2]  132.9 174.88 0 top
NOREF#4  -  [unnamed#2]  47.67 23.11 0 top
NOREF#5  -  []  -269.98 -69.29 0 top
NOREF#6  -  [unnamed#2]  2.5 186.69 0 top
NOREF#7  -  [unnamed#2]  246.26 3.81 0 top
NOREF#8  -  [unnamed#2]  238.68 5.08 90 top
NOREF#9  -  [unnamed#2]  2.5 9.53 0 top
NOREF#10  -  [unnamed#2]  2.5 181.1 0 top
NOREF#11  -  [unnamed#2]  246.26 181.1 0 top
NOREF#12  -  [unnamed#2]  79 174.88 0 top
NOREF#13  -  [unnamed#2]  236.81 10.29 0 top
NOREF#14  -  [unnamed#2]  33.94 174.88 0 top
NOREF#15  -  [unnamed#2]  196.98 176.5 90 top
NOREF#16  -  []  -128.62 -44.82 0 top
NOREF#17  -  []  0 0 0 top
NOREF#18  -  [unnamed#2]  246.26 9.53 0 top
NOREF#19  -  [unnamed#2]  7.68 10.45 0 top
NOREF#20  -  []  5 0 90 top
NOREF#21  -  []  243.76 190.5 0 top
NOREF#22  -  [unnamed#2]  201.26 45.7 0 top
NOREF#23  -  [unnamed#2]  10.08 5.08 0 top
NOREF#24  -  []  243.76 0 0 top
NOREF#25  -  [unnamed#2]  238.68 185.42 90 top
NOREF#26  -  [unnamed#2]  7.68 181.26 0 top
NOREF#27  -  []  63.02 -77.72 0 top
NOREF#28  -  [unnamed#2]  246.26 186.69 0 top
NOREF#29  -  []  5 0 0 top
NOREF#30  -  [unnamed#2]  10.08 185.42 0 top
NOREF#31  -  [unnamed#2]  2.5 181.1 180 bottom
NOREF#32  -  [unnamed#2]  246.26 181.1 180 bottom
NOREF#33  -  [unnamed#2]  115.12 138.68 180 bottom
NOREF#34  -  [unnamed#2]  236.81 10.29 180 bottom
NOREF#35  -  [unnamed#2]  7.68 10.45 180 bottom
NOREF#36  -  [unnamed#2]  97.67 138.68 180 bottom
NOREF#37  -  [unnamed#2]  2.5 9.53 180 bottom
NOREF#38  -  [unnamed#2]  151.56 138.68 180 bottom
NOREF#39  -  [unnamed#2]  61.22 138.68 180 bottom
NOREF#40  -  [unnamed#2]  7.68 181.26 180 bottom
NOREF#41  -  [unnamed#2]  246.26 9.53 180 bottom
Q1  BSS138W  [TO_SOT323-123]  11.08 154.56 0 top
Q2  BSS138W  [TO_SOT323-123]  230.53 31.93 0 top
Q3  NX3008CBKS  [SOT363-6_1-1]  157.69 47.98 90 top
Q4  NX3008CBKS  [SOT363-6_1-1]  155.23 43.84 90 top
R1  330E  [RES0402_0-5]  185.14 189.14 180 top
R2  330E  [RES0402_0-5]  188.31 189.04 180 top
R3  3K_1%  [RES0402_0-5]  191.07 189.04 180 top
R4  3K_1%  [RES0402_0-5]  193.75 189.04 180 top
R5  180E  [RES0402_0-5]  30.71 187.68 0 top
R6  0.033E_1%  [RES1210_0-75]  169.43 186.71 90 top
R7  220E_1%  [RES0402_0-5]  30.71 185.02 180 top
R8  10K  [RES0402_0-5]  159.3 180.45 90 top
R9  3.4K_1%  [RES0402_0-5]  138.45 178.77 180 top
R10  0E  [RES0402_0-5]  158.12 178.68 180 top
R11  330E  [RES0402_0-5]  181.19 178.64 90 top
R12  0E  [RES0402_0-5]  61.75 178.29 180 top
R13  16.5K_1%  [RES0402_0-5]  138.45 177.5 0 top
R14  10K_1%  [RES0402_0-5]  140.63 177.41 180 top
R15  1K_1%  [RES0402_0-5]  11.25 176.71 270 top
R16  10K_1%  [RES0402_0-5]  158.62 176.24 270 top
R17  30K  [RES0402_0-5]  29.92 175.64 90 top
R18  6.8K  [RES0402_0-5]  181.29 174.95 0 top
R19  1K_1%  [RES0402_0-5]  11.25 174.84 270 top
R20  10K  [RES0402_0-5]  59.42 174.42 0 top
R21  0E  [RES0402_0-5]  153.43 174.4 90 top
R22  4.87K_1%  [RES0402_0-5]  9.4 174.26 0 top
R23  51K  [RES0402_0-5]  29.29 174.01 0 top
R24  6.8K  [RES0402_0-5]  181.29 173.81 0 top
R25  10K  [RES0402_0-5]  59.42 173.28 0 top
R26  49.9K_1%  [RES0402_0-5]  181.29 172.67 0 top
R27  10K  [RES0402_0-5]  59.42 172.13 0 top
R28  100K  [RES0402_0-5]  177.43 171.66 0 top
R29  0E  [RES0402_0-5]  138.24 171.66 270 top
R30  0E  [RES0402_0-5]  139.39 171.66 270 top
R31  4.7K  [RES0402_0-5]  59.42 170.82 0 top
R32  10K  [RES0402_0-5]  142.73 170.67 270 top
R33  10K  [RES0402_0-5]  144 170.67 270 top
R34  10K  [RES0402_0-5]  145.27 170.67 270 top
R35  10K  [RES0402_0-5]  146.54 170.67 270 top
R36  10K  [RES0402_0-5]  147.81 170.67 270 top
R37  10K  [RES0402_0-5]  149.08 170.67 270 top
R38  10K  [RES0402_0-5]  150.35 170.67 270 top
R39  10K  [RES0402_0-5]  151.62 170.67 270 top
R40  10K  [RES0402_0-5]  152.89 170.67 270 top
R41  10K  [RES0402_0-5]  154.16 170.67 270 top
R42  100K  [RES0402_0-5]  98.12 170.4 0 top
R43  100K  [RES0402_0-5]  100.16 170.4 0 top
R44  100K  [RES0402_0-5]  124 170.4 0 top
R45  100K  [RES0402_0-5]  126.03 170.4 0 top
R46  0E  [RES0402_0-5]  41.23 169.73 180 top
R47  4.7K  [RES0402_0-5]  59.42 169.68 0 top
R48  4.7K  [RES0402_0-5]  59.42 168.54 0 top
R49  0E  [RES0402_0-5]  13.16 167.66 270 top
R51  4.7K  [RES0402_0-5]  59.42 167.39 0 top
R52  4.7K  [RES0402_0-5]  19.64 166.89 0 top
R53  0.003E_2%  [RES1206_W_0-75]  184.69 166.86 180 top
R54  10K  [RES0402_0-5]  35.65 166.53 270 top
R56  0E  [RES0402_0-5]  137.74 165.95 270 top
R57  0E  [RES0402_0-5]  138.88 165.95 270 top
R58  20K_1%  [RES0402_0-5]  58.81 165.76 90 top
R59  10K_1%  [RES0402_0-5]  60.08 165.76 90 top
R60  2.2K  [RES0402_0-5]  10.85 165.72 270 top
R61  2.2K  [RES0402_0-5]  11.99 165.72 270 top
R62  2.2K  [RES0402_0-5]  13.13 165.72 270 top
R63  2.2K  [RES0402_0-5]  14.28 165.72 270 top
R64  10K  [RES0402_0-5]  15.42 165.72 270 top
R65  4.7K  [RES0402_0-5]  106 165.69 270 top
R66  4.7K  [RES0402_0-5]  107.27 165.69 90 top
R69  330K_1%  [RES0402_0-5]  21.65 164.88 270 top
R70  220K_1%  [RES0402_0-5]  22.79 164.88 90 top
R71  200K  [RES0402_0-5]  126.68 164.54 270 top
R72  10K  [RES0402_0-5]  134.52 164.51 0 top
R73  10K  [RES0402_0-5]  35.65 164.5 90 top
R76  4.7K  [RES0402_0-5]  112.07 163.94 90 top
R77  0E  [RES0402_0-5]  34.82 162.93 90 top
R78  240E  [RES0402_0-5]  160.96 162.7 0 top
R79  4.7K  [RES0402_0-5]  62.24 162.62 0 top
R80  240E  [RES0402_0-5]  159.44 162.19 90 top
R81  0E  [RES0402_0-5]  71.14 162.07 0 top
R82  9.53K_1%  [RES0402_0-5]  73.08 162.07 180 top
R83  100E_1%  [RES0402_0-5]  33.78 161.87 270 top
R84  10K  [RES0402_0-5]  23.73 161.77 270 top
R85  10K  [RES0402_0-5]  24.88 161.77 90 top
R86  10K  [RES0402_0-5]  26.02 161.77 90 top
R87  10K  [RES0402_0-5]  27.16 161.77 90 top
R88  0E  [RES0402_0-5]  69.71 161.65 270 top
R89  0E  [RES0402_0-5]  70.72 161.65 270 top
R90  2.2K  [RES0201_0-5]  7.55 161.32 90 top
R91  0E  [RES0402_0-5]  8.72 161.23 270 top
R92  0E  [RES0402_0-5]  34.82 160.81 270 top
R93  49.9E_1%  [RES0402_0-5]  162.37 160.12 90 top
R94  1M_1%  [RES0402_0-5]  70.21 160.1 180 top
R95  0E  [RES0402_0-5]  8.72 159.35 90 top
R96  2.2K  [RES0201_0-5]  7.55 159.26 270 top
R97  10K  [RES0402_0-5]  130.97 158.61 90 top
R98  10K  [RES0402_0-5]  132.24 158.61 270 top
R99  10K  [RES0402_0-5]  86.29 158.4 90 top
R100  1K_1%  [RES0402_0-5]  142.73 158.17 90 top
R101  1K_1%  [RES0402_0-5]  144 158.17 90 top
R102  1K_1%  [RES0402_0-5]  145.27 158.17 90 top
R103  1K_1%  [RES0402_0-5]  146.54 158.17 90 top
R104  1K_1%  [RES0402_0-5]  147.81 158.17 90 top
R105  1K_1%  [RES0402_0-5]  149.08 158.17 90 top
R106  1K_1%  [RES0402_0-5]  150.35 158.17 90 top
R107  1K_1%  [RES0402_0-5]  151.62 158.17 90 top
R108  1K_1%  [RES0402_0-5]  152.89 158.17 90 top
R109  1K_1%  [RES0402_0-5]  154.16 158.17 90 top
R110  0E  [RES0402_0-5]  204.03 157.24 90 top
R111  0E  [RES0402_0-5]  205.18 157.24 270 top
R112  2.2K  [RES0201_0-5]  129.88 157.13 90 top
R113  2.2K  [RES0201_0-5]  128.91 157.11 90 top
R114  10K  [RES0402_0-5]  85.91 156.75 0 top
R115  33E_1%  [RES0402_0-5]  98.23 155.86 0 top
R116  10K  [RES0402_0-5]  13.27 155.82 90 top
R117  5.23K_1%  [RES0402_0-5]  207.58 155.36 270 top
R118  10.5E_1%  [RES0402_0-5]  202.47 155.35 0 top
R122  33E_1%  [RES0402_0-5]  104.83 154.08 270 top
R123  33E_1%  [RES0402_0-5]  105.98 154.08 270 top
R125  10K  [RES0402_0-5]  208.09 153.5 90 top
R126  33E_1%  [RES0402_0-5]  87.82 153.32 180 top
R129  49.9E_1%  [RES0402_0-5]  104.41 152.56 180 top
R130  49.9E_1%  [RES0402_0-5]  106.4 152.56 0 top
R131  33E_1%  [RES0402_0-5]  87.82 152.18 180 top
R132  10K  [RES0402_0-5]  10.01 151.58 0 top
R133  54.9K_1%  [RES0402_0-5]  208.72 151.49 0 top
R134  33E_1%  [RES0402_0-5]  98.2 151.16 0 top
R135  4.7K  [RES0402_0-5]  110.57 150.89 0 top
R136  0.002E_2%  [RES_FCSL90_3518-6_0-5_TI]  164.8 150.35 180 top
R137  10K  [RES0402_0-5]  15.05 150.2 180 top
R138  33E_1%  [RES0402_0-5]  98.2 150.02 0 top
R139  2.2K  [RES0201_0-5]  8.12 148.41 270 top
R140  2.2K  [RES0201_0-5]  10.07 148.41 270 top
R141  4.7K  [RES0402_0-5]  110.57 149.74 180 top
R142  10K  [RES0402_0-5]  12.69 149.7 180 top
R143  10K  [RES0402_0-5]  15.05 149 180 top
R144  10K  [RES0402_0-5]  12.69 148.5 180 top
R145  10K  [RES0402_0-5]  20.71 147.78 270 top
R146  4.7K  [RES0402_0-5]  21.85 147.78 90 top
R147  4.7K  [RES0402_0-5]  23 147.78 90 top
R148  10K  [RES0402_0-5]  208.72 147.18 0 top
R149  10.5E_1%  [RES0402_0-5]  202.19 145.65 180 top
R150  0E  [RES0402_0-5]  203.92 143.94 270 top
R151  0E  [RES0402_0-5]  205.06 143.94 90 top
R152  0E  [RES0402_0-5]  32.21 143.21 180 top
R153  100E_1%  [RES0402_0-5]  33.86 142.64 90 top
R154  0E  [RES0402_0-5]  191.83 95.76 0 top
R155  0E  [RES0402_0-5]  32.21 142.07 180 top
R157  10K  [RES0402_0-5]  20.71 141.78 90 top
R158  4.7K  [RES0402_0-5]  21.85 141.78 270 top
R159  4.7K  [RES0402_0-5]  23 141.78 270 top
R160  10K  [RES0402_0-5]  24.14 141.78 90 top
R161  10K  [RES0402_0-5]  25.28 141.78 270 top
R162  10K  [RES0402_0-5]  26.43 141.78 90 top
R163  10K  [RES0402_0-5]  27.57 141.78 90 top
R164  10K  [RES0402_0-5]  28.71 141.78 90 top
R165  0.003E_2%  [RES1206_W_0-75]  184.69 133.84 0 top
R166  0E  [RES0402_0-5]  133.21 132.86 180 top
R167  0E  [RES0402_0-5]  134.05 132.86 0 top
R168  0E  [RES0402_0-5]  134.05 134.13 0 top
R169  0E  [RES0402_0-5]  134.05 135.15 0 top
R170  0E  [RES0402_0-5]  133.21 134.13 180 top
R171  0E  [RES0402_0-5]  133.21 135.15 180 top
R174  0E  [RES0201_0-5]  119.09 131.81 270 top
R175  0E  [RES0201_0-5]  120 131.81 270 top
R176  0E  [RES0402_0-5]  133.21 131.72 180 top
R177  0E  [RES0402_0-5]  134.05 131.72 0 top
R178  10E_1%  [RES0402_0-5]  203.35 130.66 270 top
R179  10E_1%  [RES0402_0-5]  204.5 130.66 270 top
R180  0.005E_1%  [RES_KRL3216_1206-6_0-7_TI]  160.28 127.51 0 top
R181  0.005E_1%  [RES_KRL3216_1206-6_0-7_TI]  208.15 126.82 90 top
R182  10K  [RES0402_0-5]  48.85 125.34 0 top
R183  10K  [RES0402_0-5]  50.88 125.34 180 top
R184  100E_1%  [RES0402_0-5]  241.71 125.05 0 top
R185  0.005E_1%  [RES_KRL3216_1206-6_0-7_TI]  77.89 124.97 180 top
R186  1.8K  [RES0402_0-5]  166.27 124.93 0 top
R187  0.003E_2%  [RES1206_W_0-75]  218.09 124.59 0 top
R188  10K_1%  [RES0402_0-5]  180.22 124.46 270 top
R189  6.19K_1%  [RES0402_0-5]  181.36 124.46 90 top
R190  47.5K_1%  [RES0402_0-5]  182.51 124.46 90 top
R191  10K_1%  [RES0402_0-5]  191.6 124.41 270 top
R192  6.19K_1%  [RES0402_0-5]  192.74 124.41 90 top
R193  47.5K_1%  [RES0402_0-5]  193.89 124.41 90 top
R194  10K_1%  [RES0402_0-5]  169.02 124.38 270 top
R195  6.19K_1%  [RES0402_0-5]  170.16 124.38 90 top
R196  47K  [RES0402_0-5]  171.31 124.38 270 top
R197  6.19K_1%  [RES0402_0-5]  172.45 124.38 90 top
R198  499E_0.1%  [RES0402_0-5]  121.8 123.11 0 top
R199  10K  [RES0402_0-5]  27.03 123.89 90 top
R200  10K  [RES0402_0-5]  42.97 123.43 0 top
R201  0E  [RES0402_0-5]  163.91 123.35 180 top
R202  10K_1%  [RES0402_0-5]  17.97 123.26 270 top
R203  0E  [RES0402_0-5]  164.33 122.93 270 top
R204  10K  [RES0402_0-5]  42.97 122.16 180 top
R205  0E  [RES0402_0-5]  163.91 121.53 180 top
R206  20K_1%  [RES0402_0-5]  166.28 121.27 0 top
R207  220E_1%  [RES0402_0-5]  241.71 121.24 0 top
R208  0E  [RES0402_0-5]  164.33 121.11 270 top
R209  10K_1%  [RES0402_0-5]  109.12 118.36 180 top
R210  49.9E_1%  [RES0402_0-5]  64.19 118.05 90 top
R211  49.9E_1%  [RES0402_0-5]  52.22 117.95 180 top
R212  33E_1%  [RES0402_0-5]  54.29 117.89 180 top
R213  1K_1%  [RES0402_0-5]  72.96 117.76 180 top
R214  33E_1%  [RES0402_0-5]  62.54 117.63 0 top
R215  220E_1%  [RES0402_0-5]  241.71 117.43 0 top
R216  6.19K_1%  [RES0402_0-5]  70.72 117.13 180 top
R217  33E_1%  [RES0402_0-5]  54.29 116.87 180 top
R218  49.9E_1%  [RES0402_0-5]  52.22 116.81 180 top
R219  33E_1%  [RES0402_0-5]  62.54 116.62 0 top
R220  10K_1%  [RES0402_0-5]  72.96 116.62 0 top
R221  49.9E_1%  [RES0402_0-5]  64.19 116.2 270 top
R222  1K_1%  [RES0402_0-5]  9.24 115.98 0 top
R223  47K  [RES0402_0-5]  70.72 115.98 0 top
R224  4.7K  [RES0402_0-5]  54.29 115.86 0 top
R225  0E  [RES0402_0-5]  62.54 115.35 180 top
R226  0.01E_1%  [RES_FC4L16_0306-4_0-7]  96.47 114.9 180 top
R227  0E  [RES0402_0-5]  54.29 114.84 0 top
R228  6.19K_1%  [RES0402_0-5]  70.72 114.84 180 top
R229  10K  [RES0402_0-5]  50.22 114.68 270 top
R230  0E  [RES0402_0-5]  62.54 114.33 0 top
R231  49.9E_1%  [RES0402_0-5]  52.22 113.76 180 top
R232  10K  [RES0402_0-5]  18.47 113.7 180 top
R233  33E_1%  [RES0402_0-5]  54.29 113.7 180 top
R234  10K_1%  [RES0402_0-5]  70.72 113.7 0 top
R235  56.2K_1%  [RES0402_0-5]  109.06 113.53 180 top
R236  4.7K  [RES0402_0-5]  62.54 113.19 180 top
R237  24.9K_1%  [RES0402_0-5]  110.59 113.02 270 top
R238  33E_1%  [RES0402_0-5]  54.29 112.68 180 top
R239  49.9E_1%  [RES0402_0-5]  52.22 112.62 180 top
R240  49.9E_1%  [RES0402_0-5]  64.2 112.56 90 top
R241  10K  [RES0402_0-5]  18.47 112.43 180 top
R242  33E_1%  [RES0402_0-5]  62.55 112.06 0 top
R243  0.01E_1%  [RES_FC4L16_0306-4_0-7]  106.6 111.91 90 top
R244  0E  [RES0402_0-5]  214.76 111.18 270 top
R245  0E  [RES0402_0-5]  216.03 111.18 90 top
R246  33E_1%  [RES0402_0-5]  62.55 111.04 0 top
R247  1.8K  [RES0402_0-5]  70.09 111.03 90 top
R248  49.9E_1%  [RES0402_0-5]  64.2 110.53 270 top
R249  1K_1%  [RES0402_0-5]  9.24 110.14 0 top
R250  10K  [RES0402_0-5]  47.35 109.93 90 top
R251  10K  [RES0402_0-5]  48.62 109.93 270 top
R252  10.5E_1%  [RES0402_0-5]  217.95 109.65 0 top
R253  10K  [RES0402_0-5]  213.06 109.28 0 top
R254  10.5E_1%  [RES0402_0-5]  221.32 107.86 270 top
R255  10K  [RES0402_0-5]  211.09 107.81 180 top
R256  4.7K  [RES0402_0-5]  27.01 107.44 0 top
R257  0E  [RES0201_0-5]  54.92 106.85 0 top
R258  0E  [RES0201_0-5]  56.27 106.41 90 top
R259  0E  [RES0201_0-5]  54.92 105.96 180 top
R260  10K_1%  [RES0201_0-5]  57.36 105.95 0 top
R261  0E  [RES0201_0-5]  54.92 105.04 0 top
R262  47.5K_1%  [RES0402_0-5]  70.8 104.81 180 top
R263  0E  [RES0201_0-5]  56.27 104.59 90 top
R264  0E  [RES0201_0-5]  54.92 104.15 180 top
R265  6.19K_1%  [RES0402_0-5]  70.8 103.66 180 top
R266  49.9E_1%  [RES0402_0-5]  62.79 103.33 180 top
R267  0E  [RES0201_0-5]  54.92 103.22 0 top
R268  0E  [RES0201_0-5]  56.27 102.78 90 top
R269  10K_1%  [RES0402_0-5]  70.8 102.52 0 top
R270  0E  [RES0201_0-5]  54.92 102.33 180 top
R271  10K  [RES0402_0-5]  211.09 102.19 180 top
R272  10.5E_1%  [RES0402_0-5]  221.27 101.81 270 top
R273  0E  [RES0201_0-5]  54.92 101.4 0 top
R274  49.9K_1%  [RES0402_0-5]  166.48 101.28 0 top
R275  0E  [RES0201_0-5]  56.27 100.96 90 top
R276  0E  [RES0201_0-5]  54.92 100.52 180 top
R277  10.5E_1%  [RES0402_0-5]  217.51 100.08 180 top
R278  49.9K_1%  [RES0402_0-5]  166.48 99.91 0 top
R279  11.8K_1%  [RES0402_0-5]  212.52 99.83 180 top
R281  0E  [RES0201_0-5]  54.92 99.59 0 top
R282  0E  [RES0201_0-5]  56.27 99.14 90 top
R283  0E  [RES0201_0-5]  54.92 98.7 180 top
R284  49.9K_1%  [RES0402_0-5]  166.48 98.53 0 top
R285  0E  [RES0402_0-5]  20.24 97.92 180 top
R286  0E  [RES0402_0-5]  22.35 97.92 180 top
R287  22E_1%  [RES0402_0-5]  54.92 97.77 0 top
R288  0E  [RES0402_0-5]  215.58 97.51 90 top
R289  0E  [RES0402_0-5]  216.85 97.51 270 top
R290  0E  [RES0402_0-5]  7.37 97.42 0 top
R291  22E_1%  [RES0402_0-5]  56.27 97.33 90 top
R292  0E  [RES0201_0-5]  86.64 97.24 0 top
R293  49.9K_1%  [RES0402_0-5]  166.48 97.16 0 top
R294  0E  [RES0201_0-5]  54.92 96.88 180 top
R295  0E  [RES0402_0-5]  20.24 96.78 180 top
R296  0E  [RES0402_0-5]  22.35 96.78 180 top
R297  2.2K  [RES0201_0-5]  86.63 96.33 0 top
R298  0E  [RES0201_0-5]  54.92 95.96 0 top
R299  49.9K_1%  [RES0402_0-5]  166.48 95.79 0 top
R300  0E  [RES0402_0-5]  20.24 95.64 180 top
R301  0E  [RES0402_0-5]  22.35 95.64 180 top
R302  0E  [RES0201_0-5]  56.27 95.51 90 top
R303  2.2K  [RES0201_0-5]  86.6 95.13 0 top
R304  0E  [RES0201_0-5]  54.92 95.07 180 top
R305  0E  [RES0402_0-5]  20.24 94.5 180 top
R306  0E  [RES0402_0-5]  22.35 94.5 180 top
R307  49.9K_1%  [RES0402_0-5]  166.48 94.42 0 top
R308  0.005E_1%  [RES_KRL3216_1206-6_0-7_TI]  227.36 93.94 180 top
R309  0E  [RES0201_0-5]  54.92 94.14 0 top
R310  0E  [RES0201_0-5]  86.67 94.09 0 top
R311  0E  [RES0201_0-5]  56.27 93.7 90 top
R312  0E  [RES0402_0-5]  20.24 93.35 180 top
R313  0E  [RES0402_0-5]  22.35 93.35 180 top
R314  0E  [RES0402_0-5]  7.37 93.28 180 top
R315  0E  [RES0201_0-5]  54.92 93.25 180 top
R316  10K_1%  [RES0402_0-5]  67.88 93.98 270 top
R317  49.9K_1%  [RES0402_0-5]  166.48 93.05 0 top
R318  0E  [RES0402_0-5]  76.34 92.29 0 top
R319  0E  [RES0402_0-5]  20.24 92.21 180 top
R320  0E  [RES0402_0-5]  22.35 92.21 180 top
R321  0E  [RES0402_0-5]  7.37 92.13 180 top
R322  49.9K_1%  [RES0402_0-5]  166.48 91.68 0 top
R323  49.9E_1%  [RES0402_0-5]  196.57 86.8 0 top
R324  0E  [RES0402_0-5]  76.34 91.27 0 top
